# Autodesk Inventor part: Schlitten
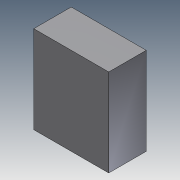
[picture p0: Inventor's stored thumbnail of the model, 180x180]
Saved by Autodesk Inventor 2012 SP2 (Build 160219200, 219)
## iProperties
Created: 2012-10
Part Number: Schlitten
Material: Standard
Description: =<BEZEICHNUNG DEUTSCH>
Document SubType Name: Modeling
Designer: Massmann
Density: 1 g/cm^3
Author: Massmann
IdentNr: =<SAP MATERIALNUMMER>
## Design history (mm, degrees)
sketch "Skizze1"
  geometry: L1 (-30, 15)-(30, 15); L2 (30, 15)-(30, -15); L3 (30, -15)-(-30, -15); L4 (-30, -15)-(-30, 15); L5 (-30, 15)-(30, -15); 2 further points
  constraints: 10 end point, 2 parallel, 1 coincident, 1 horizontal, 1 midpoint, 1 perpendicular
  dimensions: "d0" = 60 distance of L2.end L3.end; "d1" = 30 distance of L3.end L1.start
extrude "Extrusion1" new body sketch "Skizze1" stored distance "d2" = 70; taper "d3" = 0 deg
node "Volumenkörper1"
node "Volumenkörpern"
node "Oberflächenkörpern"
other parameters: "G_L" = 0.1 [user parameter], "G_B" = 0.1 [user parameter]
